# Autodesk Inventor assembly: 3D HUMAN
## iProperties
Company: Cross Bros.
Shininess: 64.0
Length Units: 11272
Angle Units: 11279
Time Units: 11290
Mass Units: 11286
Length Display Precision: 3
Angle Display Precision: 2
Compacted: True
Part Number: 3D HUMAN
Document SubType Name: Assembly
Created: 2003-03
Designer: MVF
Catalog Web Link: www.crossbros.com
Density: 0.0
Volumn: 0.0
Area: 0.0
PropertySet Name: Model Information
Control State: 0
Master: False
Checked Out: False
Author: MVF
Title: iMike
